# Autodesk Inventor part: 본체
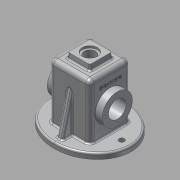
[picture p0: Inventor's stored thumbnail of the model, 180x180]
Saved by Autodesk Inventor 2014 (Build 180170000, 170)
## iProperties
Created: 2017-07
Part Number: 본체
Material: 알루미늄 6061
Document SubType Name: Modeling
Designer: 702-10
Density: 2.71 g/cm^3
Appearance: 알루미늄 - 평지
Mass: 896.814 g
Surface Area: 989.073 cm^2
Volume: 330.928 cm^3
Author: 702-10
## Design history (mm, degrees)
sketch "스케치1"
  geometry: L1 (-37, 37)-(37, 37); L2 (37, 37)-(37, -37); L3 (37, -37)-(-37, -37); L4 (-37, -37)-(-37, 37); L5 (-37, 37)-(37, -37); L6 (37, 37)-(-37, -37); 1 further point
  constraints: 12 end point, 2 midpoint, 2 parallel, 1 horizontal, 1 perpendicular
  dimensions: "d1" = 74 distance of L1.end L2.end; "d2" = 74 distance of L2.end L3.end
extrude "돌출1" new body sketch "스케치1" distance "d3" = 110; taper "d4" = 0 deg
sketch "스케치2"
  geometry: L1 (37, -37)-(37, 37) reference; L2 (0, 0)-(0, 65); L3 (0, 0)-(75, 0); 1 further point; 1 other entity
  constraints: 4 end point, 1 coincident, 1 horizontal, 1 parallel, 1 perpendicular, 4 other
  dimensions: "d7" = 65 distance of L2.start L2.end; "d8" = 75 distance of L2.start L3.end
extrude "돌출2" join sketch "스케치2" distance "d9" = 10; taper "d10" = 0 deg
fillet "모깎기1" dims "d11" = 8
fillet "모깎기2" dims "d12" = 8
feature "쉘1" dims "d13" = 10, "d14" = 5
sketch "스케치3"
  geometry: L1 (-29, 110)-(29, 110) reference; L2 (37, 102)-(37, 10) reference; L3 (37, 10)-(75, 10) reference; L4 (75, 10)-(75, 0) reference; L5 (75, 0)-(32, 0) reference; L6 (32, 0)-(32, 102) reference; L7 (29, 105)-(-29, 105) reference; L8 (-32, 102)-(-32, 0) reference; L9 (-32, 0)-(-75, 0) reference; L10 (-75, 0)-(-75, 10) reference; L11 (-75, 10)-(-37, 10) reference; L12 (-37, 10)-(-37, 102) reference; L13 (0, 0)-(0, 55); L14 (0, 55)-(-32, 55); L15 (0, 55)-(32, 55); L16 (32, 82.5)-(24.202, 76.156); L17 (24.202, 76.156)-(24.202, 55); L18 (-32, 82.5)-(-25, 75.5); L19 (-25, 75.5)-(-25, 55); L20 (-32, 82.5)-(-32, 55); A1 r 8 centre (-29, 102) between (-29, 110) and (-37, 102) reference; A2 r 8 centre (29, 102) between (37, 102) and (29, 110) reference; A3 r 3 centre (29, 102) between (32, 102) and (29, 105) reference; A4 r 3 centre (-29, 102) between (-29, 105) and (-32, 102) reference
  constraints: 16 end point, 6 point on line, 4 perpendicular, 1 parallel
  dimensions: "d15" = 55 distance of L13.start L13.end; "d16" = 55 diameter of L16.start L15; "d17" = 7 distance between parallel lines of L19 L8; "d18" = 55 diameter of L18.start L14; "d19" = 135 deg angle of L19 L18
revolve "회전1" sketch "스케치3" stored, may be unused: angle "d20" = 90 deg
fillet "모깎기3" dims "d21" = 0.5
sketch "스케치4"
  geometry: L1 (-37, 29)-(-37, -29) reference; L2 (-58, 0)-(58, 0); C1 r 5 at (-58, 0); C2 r 5 at (58, 0); 2 further points; 1 other entity
  constraints: 3 coincident, 2 centre point, 2 end point, 1 midpoint, 1 perpendicular, 1 other
  dimensions: "d22" = 116 distance of L2.start L2.end; "d23" = 10 diameter of C1; "d24" = 10 diameter of C2
extrude "돌출3" cut sketch "스케치4" stored distance "d25" = 10; taper "d26" = 0 deg
fillet "모깎기4" dims "d27" = 3
sketch "스케치5"
  geometry: L1 (58, 92)-(58, 0) reference; L2 (29, -10)-(29, 45); C1 r 27.5 at (29, 45)
  constraints: 2 end point, 1 centre point, 1 coincident, 1 parallel
  dimensions: "d28" = 55 distance of L2.start L2.end; "d29" = 55 diameter of C1
extrude "돌출4" join sketch "스케치5" distance "d30" = 13; taper "d31" = 0 deg
fillet "모깎기5" dims "d32" = 0.5
sketch "스케치6"
  geometry: C1 r 27.5 at (0, 0) reference; C2 r 16 at (0, 0); 1 further point
  constraints: 1 centre point, 1 coincident
  dimensions: "d33" = 32 diameter of C2
extrude "돌출5" cut sketch "스케치6" stored distance "d34" = 13; taper "d35" = 0 deg
node "작업 평면1"
sketch "스케치7"
  geometry: L1 (20, -20)-(-20, -20); L2 (-20, -20)-(-20, 20); L3 (-20, 20)-(20, 20); L4 (20, 20)-(20, -20); L5 (20, -20)-(-20, 20); L6 (-20, -20)-(20, 20); 1 further point
  constraints: 12 end point, 2 midpoint, 2 parallel, 1 horizontal, 1 perpendicular
  dimensions: "d37" = 40 distance of L2.end L3.end; "d38" = 40 distance of L1.end L2.end
extrude "돌출6" join sketch "스케치7" stored distance "d39" = 13; taper "d40" = 5 deg
fillet "모깎기6" dims "d41" = 3
fillet "모깎기7" dims "d42" = 3
sketch "스케치8"
  geometry: 2 further points
  constraints: 1 coincident
hole "구멍1" sketch "스케치8" at (0, 0) diameter "d43" = 21; stored, may be unused: countersink angle "d47" = 90 deg, drill point angle "d49" = 118 deg; dims "d44" = 6, "d45" = 28, "d46" = 4, "d48" = 8
fillet "모깎기8" dims "d50" = 3
sketch "스케치9" dims "d51" = 45
  geometry: C1 r 27.5 at (0, 0) reference; 3 further points
  constraints: 2 vertical alignment, 1 coincident, 2 other
hole "구멍2" sketch "스케치9" at (0, 22.5) diameter "d52" = 3.242; stored, may be unused: countersink angle "d56" = 90 deg, drill point angle "d58" = 118 deg; dims "d53" = 8, "d54" = 28, "d55" = 4, "d57" = 10
sketch "스케치10"
  geometry: L1 (0, -32)-(102, -32) reference; L2 (105, -29)-(105, -10.5) reference; L3 (105, -10.5)-(116, -10.5) reference; L4 (116, -10.5)-(116, -14) reference; L5 (116, -14)-(120, -14) reference; L6 (120, -14)-(120, -20) reference; L7 (120, -20)-(112.739, -20.635) reference; L8 (110, -23.624)-(110, -29) reference; L9 (102, -37)-(13, -37) reference; L10 (10, -40)-(10, -62) reference; L11 (7, -65)-(0, -65) reference; L12 (0, -65)-(0, -32) reference; L13 (102, 32)-(0, 32) reference; L14 (0, 32)-(0, 65) reference; L15 (0, 65)-(7, 65) reference; L16 (10, 62)-(10, 40) reference; L17 (13, 37)-(102, 37) reference; L18 (110, 29)-(110, 23.624) reference; L19 (112.739, 20.635)-(120, 20) reference; L20 (120, 20)-(120, 14) reference; L21 (120, 14)-(116, 14) reference; L22 (116, 14)-(116, 10.5) reference; L23 (116, 10.5)-(105, 10.5) reference; L24 (105, 10.5)-(105, 29) reference; L25 (10, 55)-(82.194, 37); A1 r 3 centre (102, -29) between (102, -32) and (105, -29) reference; A2 r 3 centre (113, -23.624) between (112.739, -20.635) and (110, -23.624) reference; A3 r 8 centre (102, -29) between (102, -37) and (110, -29) reference; A4 r 3 centre (13, -40) between (13, -37) and (10, -40) reference; A5 r 3 centre (13, 40) between (10, 40) and (13, 37) reference; A6 r 8 centre (102, 29) between (110, 29) and (102, 37) reference; A7 r 3 centre (113, 23.624) between (110, 23.624) and (112.739, 20.635) reference; A8 r 3 centre (102, 29) between (105, 29) and (102, 32) reference; 1 further point
  constraints: 2 end point, 2 point on line, 2 other
  dimensions: "d62" = 10 distance from line of L25.start L15; "d63" = 14 deg angle of L15 L25
feature "리브1" sketch "스케치10" dims "d64" = 1, "d65" = 10, "d66" = 0, "d67" = 0, "d68" = 1, "d69" = 1
fillet "모깎기9" dims "d70" = 3
fillet "모깎기10" dims "d71" = 3
fillet "모깎기11" dims "d72" = 3
fillet "모깎기12" dims "d73" = 3
node "작업 평면2"
sketch "스케치11"
  geometry: L1 (46.011, 18)-(11.989, 18) reference; L2 (66, -89)-(66, 0) reference; 2 further points
  constraints: 1 other
  dimensions: "d75" = 30 distance from line of L1 point (29, -12); "d76" = 37 distance from line of point (29, -12) L2
feature "엠보싱1" sketch "스케치11" dims "d77" = 0.5, "d78" = 0
node "솔리드1"
mirror "대칭1"
mirror "대칭2"
pattern_circular "원형 패턴1" dims angle "d60" = 360 deg
mirror "대칭3"
mirror "대칭4"
node "절단 모서리 투영1"
node "절단 모서리 투영2"
other parameters: "d74" = 18.75
